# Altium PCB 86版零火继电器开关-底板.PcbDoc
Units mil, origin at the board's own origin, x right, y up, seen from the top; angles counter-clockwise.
Board outline 2181.33 x 2307.03 mil, 2 copper layers (Top Layer, Bottom Layer); 71 components, 44 nets, 206 pads, 150 vias.
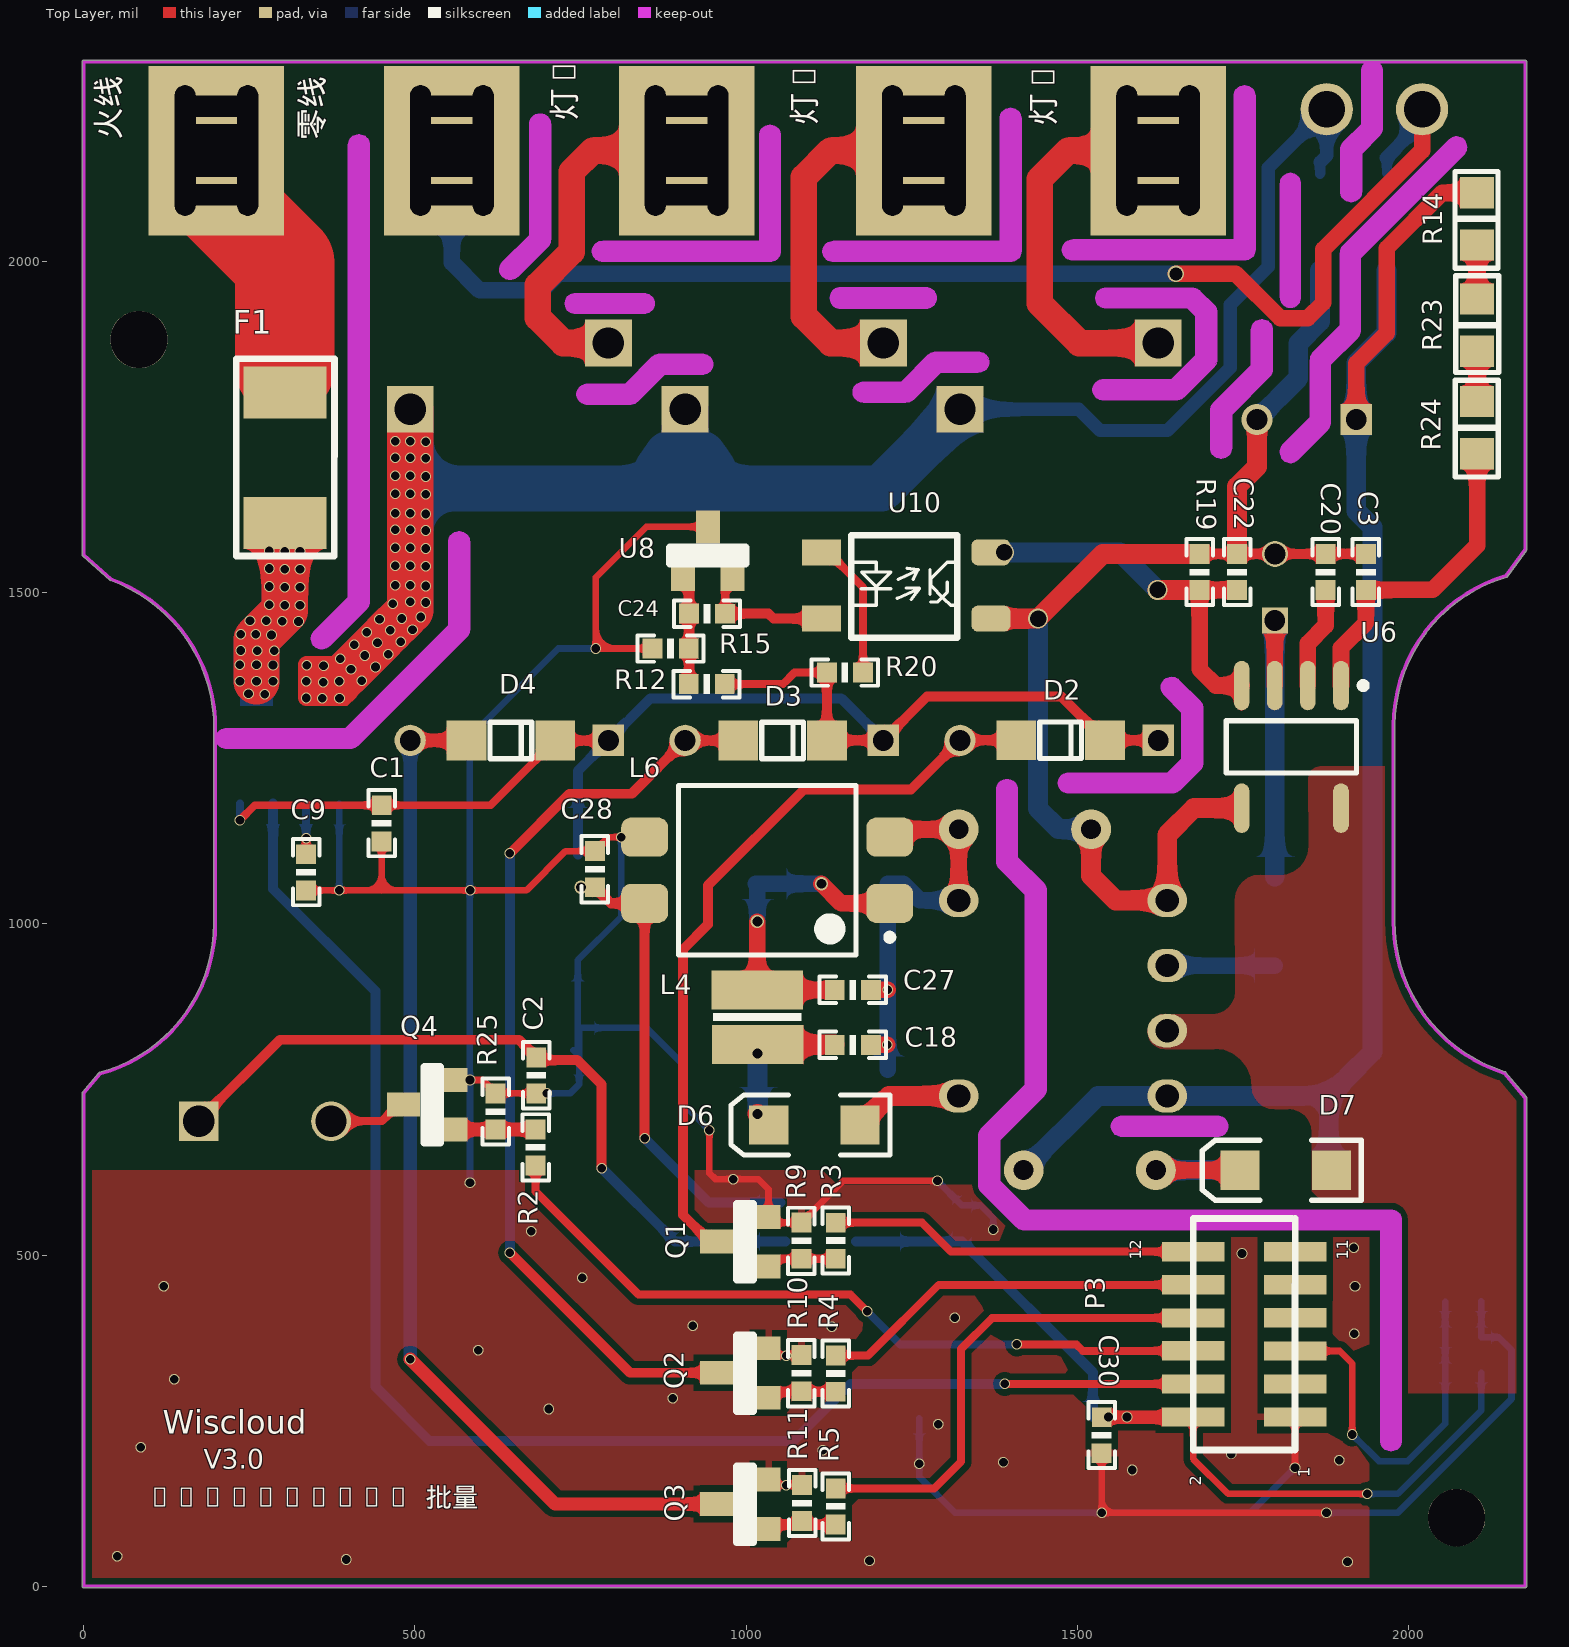
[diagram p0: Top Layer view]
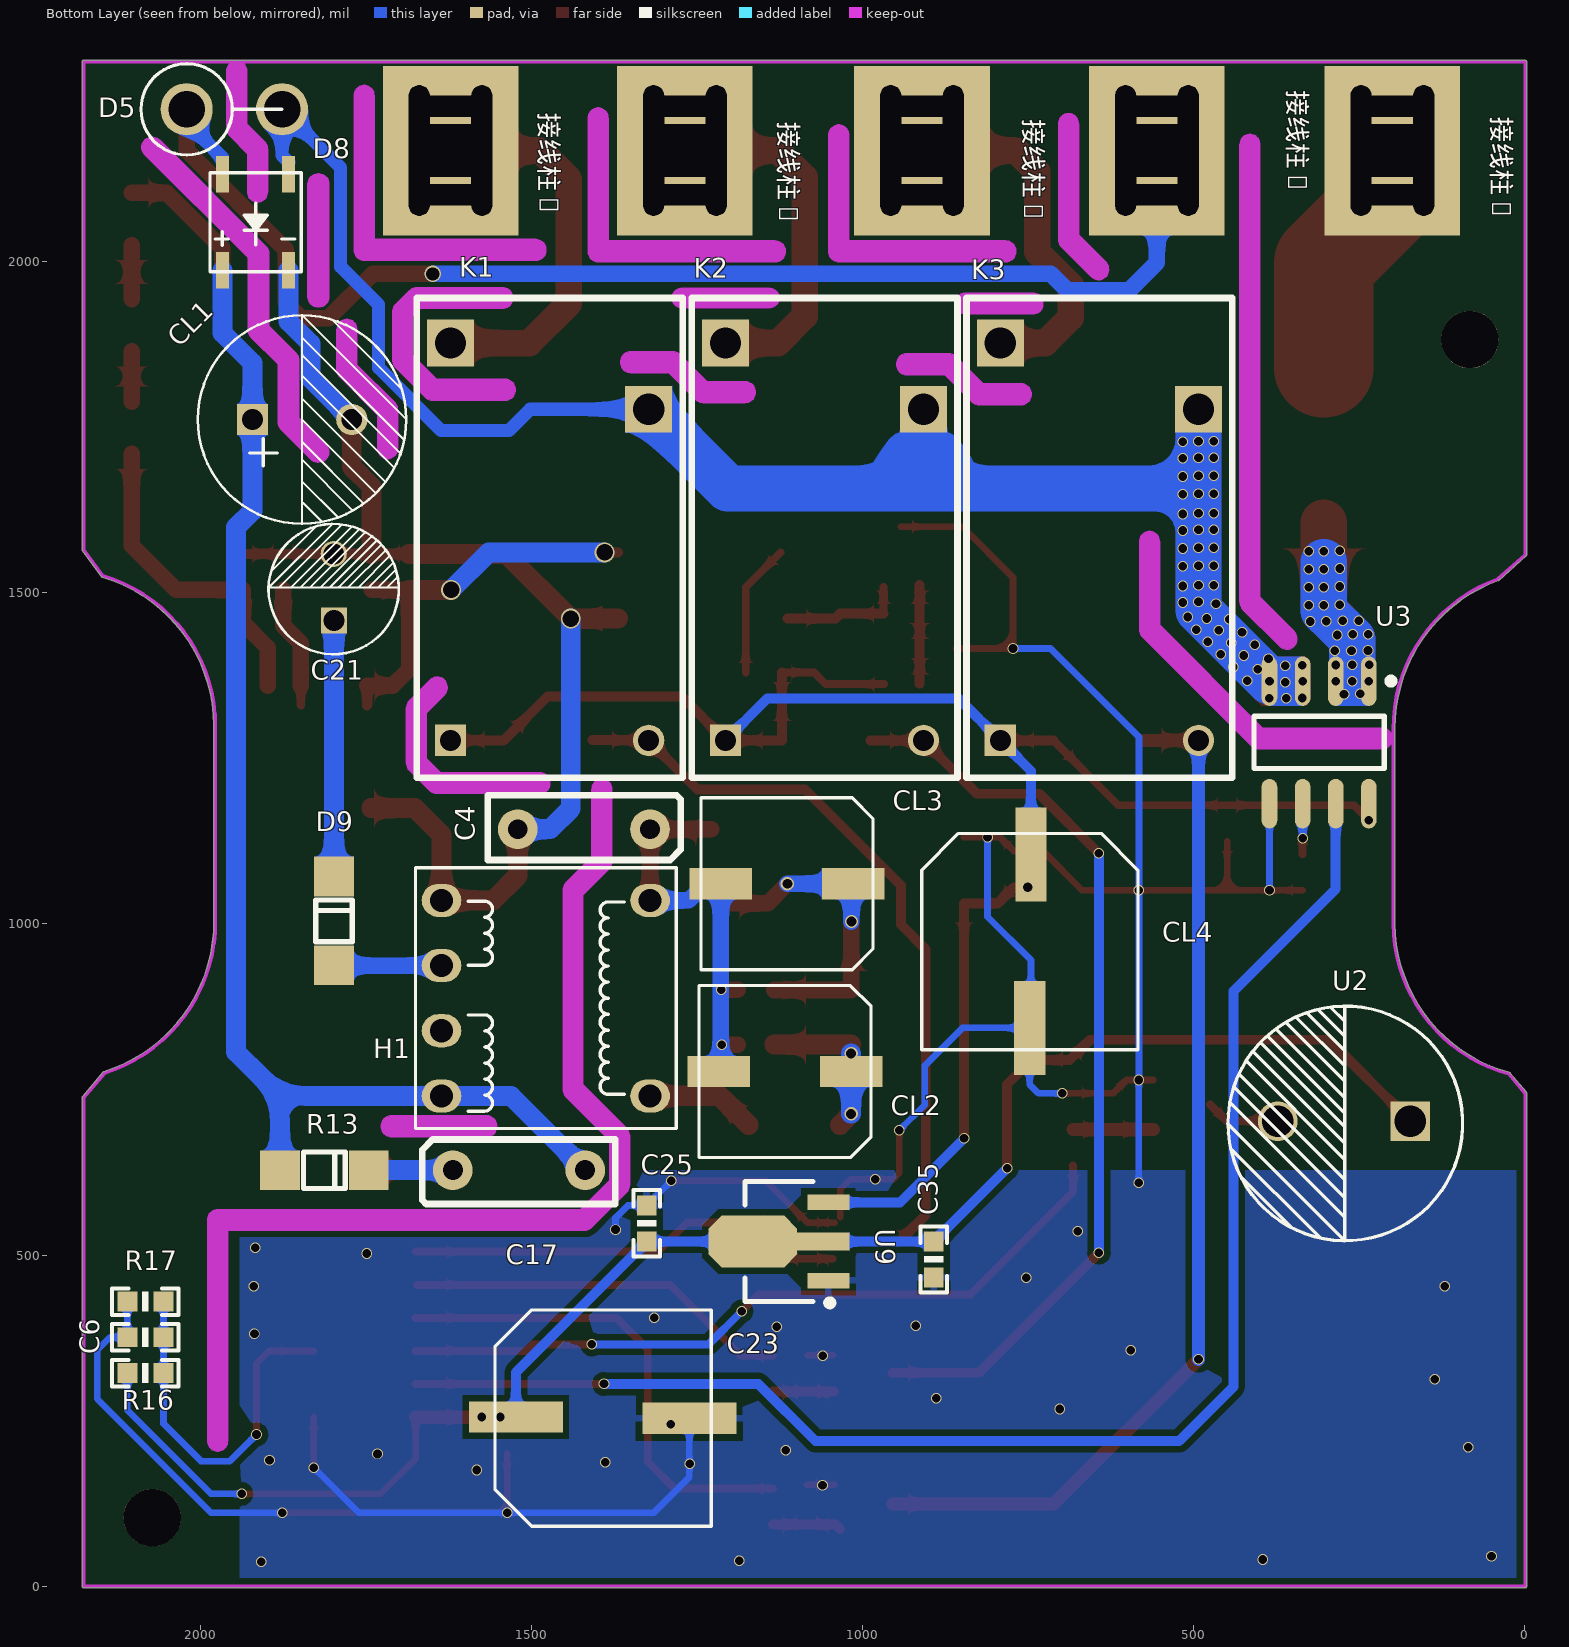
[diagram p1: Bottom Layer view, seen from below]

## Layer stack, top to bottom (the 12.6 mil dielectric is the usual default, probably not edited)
Top Solder: solder mask 0.4, Solder Resist, Dk 3.5
Top Layer: signal copper 1.4
Dielectric1: dielectric 12.6, FR-4, Dk 4.8
Bottom Layer: signal copper 1.4
Bottom Solder: solder mask 0.4, Solder Resist, Dk 3.5

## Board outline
-2.52,0 ccw(c0,0) 0.7,-2.42 ccw(c1.4,0) 1.4,-2.52 2176.3,-2.52 ccw(c2176.3,0) 2178.81,0 2178.81,737.5 ccw(c2176.3,737.5) 2178.23,739.12 2178.22,739.12 cw(c2176.3,737.5) 2178.23,739.11 2178.22,739.12 2147.11,776.25 2147.1,776.26 cw(c2145.17,774.64) 2147.11,776.25 2147.1,776.26 ccw(c2145.17,774.64) 2145.93,777.04 cw(c2217.11,1003.35) 1979.87,1004.79 ccw(c1977.36,1004.81) 1979.87,1004.81 1979.87,1299.99 cw(c2214.26,1298.6) 2148.26,1523.51 cw(c2214.26,1298.6) 2148.28,1523.51 2148.26,1523.51 ccw(c2147.57,1525.93) 2149.6,1524.44 2178.33,1563.61 ccw(c2176.3,1565.1) 2178.81,1565.1 2178.81,2302 ccw(c2176.3,2302) 2176.3,2304.51 0,2304.51 ccw(c0,2302) -2.52,2302 -2.52,1557.7 ccw(c0,1557.7) -1.68,1555.83 39.28,1519.2 ccw(c40.95,1521.07) 40.12,1518.7 ccw(c-40.79,1295.71) 40.1,1518.71 40.12,1518.7 cw(c-40.79,1295.71) 196.42,1295.71 cw(c-40.79,1295.71) 196.42,1294.33 cw(c-40.79,1295.71) 196.42,1294.31 196.42,1294.29 cw(c198.93,1294.29) 196.42,1294.33 196.42,1294.29 196.42,1000.5 cw(c-37.96,1001.89) 23.78,775.79 cw(c-37.96,1001.89) 23.75,775.78 ccw(c24.42,773.35) 22.48,774.96 22.49,774.98 cw(c24.42,773.35) 23.78,775.79 22.48,774.96 -1.91,746.03 -1.92,746.02 -1.91,746.03 ccw(c0,744.4) -2.52,744.4
cut-out: 1356.12,594.68 cw(c1367.24,605.85) 1351.48,605.85 1351.48,680.13 cw(c1367.24,680.13) 1356.12,691.3 1356.09,691.28 1421.8,756.98 1421.8,1044.24 1382.9,1083.14 1382.92,1083.11 cw(c1394.05,1094.28) 1378.28,1094.28 1378.28,1202.85 cw(c1394.05,1202.85) 1409.81,1202.85 1409.81,1100.81 1448.71,1061.91 1448.68,1061.94 cw(c1437.56,1050.77) 1453.32,1050.77 1453.32,750.45 cw(c1437.56,750.45) 1448.68,739.28 1448.71,739.31 1383,673.6 1383,612.38 1426.64,568.74 1974.12,568.74 cw(c1974.12,552.98) 1989.89,552.98 1989.89,219.57 cw(c1974.12,219.57) 1958.36,219.57 1958.36,537.21 1420.11,537.21 cw(c1420.11,552.98) 1408.94,541.85 1408.97,541.83
cut-out: 1487.4,1197.22 cw(c1487.4,1212.98) 1487.4,1228.74 1637.14,1228.74 1658.26,1249.86 1658.26,1319.36 1631.48,1346.15 cw(c1642.62,1357.29) 1653.77,1368.44 1685.17,1337.04 1685.14,1337.06 cw(c1674.02,1325.89) 1689.78,1325.89 1689.78,1243.33 cw(c1674.02,1243.33) 1685.14,1232.17 1685.17,1232.19 1654.81,1201.83 1654.84,1201.86 cw(c1643.67,1212.98) 1643.67,1197.22
cut-out: 215.76,1264.42 cw(c215.76,1280.18) 215.76,1295.95 395.76,1295.95 551.05,1451.24 551.05,1577.22 cw(c566.81,1577.22) 582.57,1577.22 582.57,1444.71 cw(c566.81,1444.71) 577.93,1433.54 577.96,1433.56 413.43,1269.04 413.46,1269.06 cw(c402.29,1280.18) 402.29,1264.42
cut-out: 1810.85,1723.61 ccw(c1821.99,1712.47) 1833.14,1701.32 1878.44,1746.62 1878.42,1746.6 ccw(c1867.29,1757.77) 1883.06,1757.77 1883.06,1844.94 1923.74,1885.62 1923.72,1885.6 ccw(c1912.6,1896.77) 1928.36,1896.77 1928.36,2006.1 2084.22,2161.96 ccw(c2073.07,2173.1) 2088.83,2173.1 ccw(c2073.07,2173.1) 2061.92,2184.25 1901.5,2023.83 ccw(c1912.65,2012.68) 1901.36,2023.68 cw(c1912.6,2012.62) 1901.5,2023.83 1901.36,2023.68 ccw(c1912.6,2012.62) 1896.83,2012.62 1896.83,1903.3 1856.15,1862.62 1856.17,1862.64 ccw(c1867.29,1851.47) 1851.53,1851.47 1851.53,1764.3
cut-out: 1898.13,2105.8 1898.13,2169.86 cw(c1913.89,2169.86) 1902.77,2181.03 1902.75,2181.01 1929.57,2207.83 1929.57,2288.24 cw(c1945.33,2288.24) 1961.09,2288.24 1961.09,2202.3 cw(c1945.33,2202.3) 1959.04,2194.53 cw(c1944.4,2200.38) 1955.55,2189.23 1929.66,2163.34 1929.66,2105.8 cw(c1913.89,2105.8)
cut-out: 1131.88,1999.97 cw(c1131.88,2015.73) 1131.88,2031.5 1383.76,2031.5 1383.76,2216.8 cw(c1399.53,2216.8) 1415.29,2216.8 1415.29,2015.73 cw(c1399.53,2015.73) 1399.53,1999.97
cut-out: 1493.45,2002.18 cw(c1493.45,2017.94) 1493.45,2033.71 1737.14,2033.71 1737.14,2250.7 cw(c1752.91,2250.7) 1768.67,2250.7 1768.67,2017.94 cw(c1752.91,2017.94) 1752.91,2002.18
cut-out: 1806.31,1946.74 ccw(c1822.07,1946.74) 1837.83,1946.74 1837.83,2117.87 ccw(c1822.07,2117.87) 1806.31,2117.87
cut-out: 1701.67,1718.59 1701.67,1775.91 cw(c1717.43,1775.91) 1706.31,1787.08 1706.28,1787.06 1763.28,1844.06 1763.28,1897.42 cw(c1779.04,1897.42) 1794.81,1897.42 1794.81,1837.53 cw(c1779.04,1837.53) 1790.17,1826.36 1790.19,1826.38 1733.19,1769.38 1733.19,1718.59 cw(c1717.43,1718.59)
cut-out: 1539.69,1822.51 1643.26,1822.51 1679.33,1858.58 1679.33,1917.46 1667.15,1929.63 1543.9,1929.63 cw(c1543.9,1945.39) 1543.9,1961.16 1673.68,1961.16 cw(c1673.68,1945.39) 1684.85,1956.52 1684.83,1956.54 1706.24,1935.13 1706.21,1935.16 cw(c1695.09,1923.99) 1710.85,1923.99 1710.85,1852.05 cw(c1695.09,1852.05) 1706.21,1840.88 1706.24,1840.9 1660.94,1795.6 1660.96,1795.63 cw(c1649.79,1806.75) 1649.79,1790.98 1539.69,1790.98 cw(c1539.69,1806.75)
cut-out: 1177.31,1787.35 cw(c1177.31,1803.11) 1177.31,1818.87 1234.84,1818.87 1275.53,1859.56 1275.5,1859.53 cw(c1286.67,1848.41) 1286.67,1864.17 1350.74,1864.17 cw(c1350.74,1848.41) 1366.5,1848.41 cw(c1350.74,1848.41) 1350.74,1832.65 1293.2,1832.65 1252.52,1791.96 1252.54,1791.99 cw(c1241.37,1803.11) 1241.37,1787.35
cut-out: 760.48,1784.23 cw(c760.48,1799.99) 760.48,1815.76 818.01,1815.76 858.7,1856.44 858.67,1856.42 cw(c869.84,1845.29) 869.84,1861.06 933.91,1861.06 cw(c933.91,1845.29) 949.67,1845.29 cw(c933.91,1845.29) 933.91,1829.53 876.37,1829.53 835.69,1788.85 835.71,1788.87 cw(c824.54,1799.99) 824.54,1784.23
cut-out: 742.77,1921.33 cw(c742.77,1937.1) 742.77,1952.86 845.64,1952.86 cw(c845.64,1937.1) 861.41,1937.1 cw(c845.64,1937.1) 845.64,1921.33
cut-out: 1142.32,1929.63 1272.11,1929.63 ccw(c1272.11,1945.39) 1287.87,1945.39 ccw(c1272.11,1945.39) 1272.11,1961.16 1142.32,1961.16 ccw(c1142.32,1945.39)
cut-out: 783.85,2000.09 cw(c783.85,2015.85) 783.85,2031.61 1020.42,2031.61 1020.42,2191.12 cw(c1036.19,2191.12) 1051.95,2191.12 1051.95,2015.85 cw(c1036.19,2015.85) 1036.19,2000.09
cut-out: 654.98,1977.43 cw(c643.83,1988.57) 632.69,1999.72 673.37,2040.4 673.37,2208.02 cw(c689.13,2208.02) 704.9,2208.02 704.9,2033.87 cw(c689.13,2033.87) 700.26,2022.7 700.28,2022.73
cut-out: 370.57,1419.5 cw(c359.42,1430.65) 348.27,1441.8 399.62,1493.15 399.62,2176.79 cw(c415.39,2176.79) 431.15,2176.79 431.15,1486.62 cw(c415.39,1486.62) 426.51,1475.45 426.53,1475.47
cut-out: 1567.63,678.76 cw(c1567.63,694.53) 1567.63,710.29 1712.05,710.29 cw(c1712.05,694.53) 1727.81,694.53 cw(c1712.05,694.53) 1712.05,678.76

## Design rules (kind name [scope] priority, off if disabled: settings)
Clearance [All] p1: gap=10 ignorepadtopadclearanceinfootprint=FALSE except(0: Arc-Hole Track-Hole SMDPad-Hole THPad-Hole Via-Hole Fill-Hole Poly-Hole Region-Hole Text-Hole)
HoleSize [All] p1: absolutevalues=TRUE maxlimit=300 minlimit=1 maxpercent=80.000 minpercent=20.000
MinimumSolderMaskSliver [All] p1: minsoldermaskwidth=7
PlaneConnect [InNet('GND')] p1: planeconnectstyle=Direct reliefexpansion=20 reliefentries=4 reliefconductorwidth=10 reliefairgap=10
PolygonConnect via [IsVia] p1: connectstyle=Direct reliefconductorwidth=10 reliefentries=4 polygonreliefangle="90 Angle" airgapwidth=10
PolygonConnect "GND _PAD" [InNet('GND')] p2: connectstyle=Relief reliefconductorwidth=10 reliefentries=4 polygonreliefangle="90 Angle" airgapwidth=10
PolygonConnect PolygonConnect_1 [All] p3: connectstyle=Direct reliefconductorwidth=10 reliefentries=4 polygonreliefangle="90 Angle" airgapwidth=10
RoutingVias [All] p1: holewidth=13 width=16 viastyle="Through Hole" minholewidth=12 minwidth=15 maxholewidth=28 maxwidth=50
SilkToSilkClearance [All] p1: silktosilkclearance=2
SilkToSolderMaskClearance [IsPad] p1: minsilkscreentomaskgap=2 clearancetoexposedcopper=TRUE
SolderMaskExpansion [All] p1: expansion=4
Width [All] p1: maxlimit=200 minlimit=10 preferedwidth=12
25 further rules are at their usual default settings.

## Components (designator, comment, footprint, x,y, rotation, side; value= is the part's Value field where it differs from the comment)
C1 "106" 0603P 449.83,1179.29 r270 top
C2 "104" 0603P 683.27,798.64 r270 top
C3 "103" 0603p 1936.11,1504.44 r90 top
C4 "471/1KV" 200mil 1521.09,1142.98 r0 bottom
C6 "104" 0603P 2110.51,375.9 r180 bottom
C9 "2.2uF" 0603P 335.77,1105.31 r270 top
C17 "222" 200mil 1419.24,628.28 r180 bottom
C18 "104" 0603P 1134.08,817.42 r0 top
C20 "330P" 0603P 1875.33,1504.44 r90 top
C21 "25V/47UF" CAP5*2 1795.78,1509.74 r90 bottom value=4.7uF/400V
C22 "103" 0603P 1741.58,1504.44 r90 top
C23 "6.3V1000uF" CAP8*10.2 1523.76,255.46 r90 bottom
C24 "103" 0603p 914.02,1468.67 r0 top
C25 "104" 0603P 1326.21,574.98 r270 bottom value=0.1uF
C27 "104" 0603P 1134.08,900.48 r0 top
C28 "104" 0603P 771.75,1055.53 r90 top
C30 "104" 0603P 1537.17,255.2 r270 top
C35 "104" 0603P 892.68,520.48 r270 bottom
CL1 "4.7uf/400V" CAP8*12 1921.62,1761.7 r180 bottom value=4.7uF/400V
CL2 "50V47uF" CAP6.3*5.4 1017.52,777.17 r270 bottom value=4.7uF/400V
CL3 "16V220uF" CAP6.3*5.4 1014.56,1060.79 r270 bottom value=4.7uF/400V
CL4 "10V/1000UF" CAP8*10.2 746.01,1105.07 r180 bottom value=4.7uF/400V
D2 "1N4148" 1206 1408.15,1277.54 r0 top
D3 "1N4148" 1206 988.31,1277.07 r0 top
D4 "1N4148" 1206 577.91,1277.07 r0 top
D5 "P6KE550AC" DO-15立式 2020.97,2229.89 r180 bottom
D6 "SS110" 3.2X1.6X1.1 1103.18,696.6 r180 top
D7 "RS1M" 3.2X1.6X1.1 1815.08,628.12 r180 top
D8 "LX10M" MBCN 1866.98,1986.89 r0 bottom
D9 "1N4148" 1206 1798.53,937.79 r90 bottom
F1 "250V/10A" 2410 304.74,1606.82 r90 top
H1 "EE10立式4+2" EE10-6 1641.26,782.54 r180 bottom
K1 "HRS3FNH-S-DC5V-A" SJ-S-105 1622.5,1277.29 r90 bottom
K2 "HRS3FNH-S-DC5V-A" SJ-S-105 1207.32,1277.29 r90 bottom
K3 "HRS3FNH-S-DC5V-A" SJ-S-105 792.15,1277.29 r90 bottom
L4 "10uH" CD32NP 1017.12,858.72 r90 top
L6 "ZJYS51R5-2PT-01" SOP-4N 1031.54,1081.22 r180 top
P3 "贴片排母" 贴片排母1.27MM2*6 1675.83,206.13 r90 top locked
Q1 "SS8050" SOT23 1033.94,482.76 r90 top
Q2 "SS8050" SOT23 1033.94,284.54 r90 top
Q3 "SS8050" SOT23 1033.94,86.32 r90 top
Q4 "SS8050" SOT23 561.38,689.58 r90 top
R2 "330Ω" 0603P 682.24,689.68 r270 top
R3 "510Ω" 0603P 1135.57,548.92 r270 top
R4 "510Ω" 0603P 1135.57,348.21 r270 top
R5 "510Ω" 0603P 1135.57,147.49 r270 top
R9 "4.7K" 0603P 1083.53,494.47 r90 top
R10 "4.7K" 0603P 1083.53,294.41 r90 top
R11 "4.7K" 0603P 1084.72,98.43 r90 top
R12 "3K/1%" 0603P 913.45,1362.23 r0 top value=100k
R13 "100K" 1206 1880.04,628.12 r180 bottom value=100k
R14 "680K" 0805 2103.77,2025.42 r90 top value=100k
R15 "2.4K" 0603P 859.02,1416.07 r0 top value=100k
R16 "10K欧姆" 0603p 2110.51,321.95 r180 bottom
R17 "2K" 0603P 2110.51,429.86 r180 bottom
R19 "10K" 0603P 1684.96,1504.44 r90 top value=100k
R20 "100Ω" 0603P 1122.17,1379.84 r0 top value=100k
R23 "680K" 0805 2103.86,1943.8 r270 top value=100k
R24 "680K" 0805 2103.96,1710.17 r90 top value=100k
R25 "4.7K" 0603P 621.86,689.64 r90 top
U2 "SPEAK" Speak-9*5.5 273.38,702.29 r0 bottom
U3 "ACS712-5" SO8_L 310.77,1274.3 r270 bottom
U6 "THX208H" SO8_L_6 1755.82,1406.15 r270 top
U8 "TL431" SOT23 904.88,1521.06 r0 top
U9 "LM1117-3.3V" SOT89M 1126.59,520.48 r0 bottom
U10 "356T-WC" "SOP4 - EL357N" 1113.96,1561.22 r0 top
接线柱1 "接线柱" 5*6*10 200.21,2168 r0 bottom locked
接线柱2 "接线柱" 5*6*10 555.8,2168 r0 bottom locked
接线柱3 "接线柱" 5*6*10 910.5,2168 r0 bottom locked
接线柱4 "接线柱" 5*6*10 1268.5,2168 r0 bottom locked
接线柱5 "接线柱" 5*6*10 1622.5,2168 r0 bottom locked

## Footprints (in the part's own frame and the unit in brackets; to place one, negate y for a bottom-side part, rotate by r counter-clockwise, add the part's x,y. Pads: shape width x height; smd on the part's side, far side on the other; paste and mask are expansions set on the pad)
3.2X1.6X1.1 [mm] "SMT LED; 2 Flat Leads"
  rect 1.5x1.5 smd: 1(-1.75,0) 2(1.75,0)
  silkscreen extent -2.9,-1.15 3.2,1.15, body extent -2.29,-1.43 2.31,1.27, height 2.4
5*6*10 [mm]
  oval 0.8x5 hole 0.8 slot 5 at 90 deg: 1(-1.201,-0.003) 1(1.201,-0.003)
  oval 3.2x0.8 hole 0.8 slot 3.2 at 0 deg: 1(0,-1.699) 1(0,1.699)
  rect 5.2x6.5 hole 2 square: 1(0,0)
200mil [mil]
  round 60 hole 30: 1(0,0) 2(-199.8,0)
  silkscreen extent -246,-51 45,46, body extent -208,-41 12,49, height 242
0603P [mil] "Chip Capacitor, 2-Leads, Body 1.6x0.8mm, IPC Medium Density"
  rect 30x30 smd: 1(0,0) 2(54.5,-0.06)
  silkscreen extent -23,-20 77,20
0603p [mil] "Chip Capacitor, 2-Leads, Body 1.6x0.8mm, IPC Medium Density"
  rect 30x30 smd: 1(0,0) 2(54.5,-0.06)
  silkscreen extent -23,-20 77,20, body extent -6,-16 57,16, height 18
0805 [mm]
  rect 1.2x1.3 smd: 1(0,0) 2(2,0)
  silkscreen extent -0.89,-0.81 2.82,0.84, body extent 0.01,-0.63 2.01,0.63, height 0.55
1206 [mil]
  rect 60x60 smd: 1(0,0) 2(133.86,0)
  silkscreen extent 35,-28 98,28
2410 [mm]
  rect 2x3.18 smd: 1(-0.028,0.027) 2(4.972,0.027)
  silkscreen extent -1.3,-1.87 6.27,1.9
CAP5*2 [mm]
  rect 1x1 hole 0.8: 1(-1.31,0.07)
  round 1 hole 0.8: 2(1.25,0.08)
  silkscreen extent -2.6,-2.42 2.4,2.58
CAP6.3*5.4 [mm]
  rect 1.2x2.4 smd: 1(0,0) 2(0.001,-5.074)
  silkscreen extent -3.3,-5.84 3.3,0.76
CAP8*10.2 [mm]
  rect 1.2x3.6 smd: 1(0,0) 2(-0.051,-6.655)
  silkscreen extent -4.19,-7.49 4.11,0.8, body extent -4.36,-8.15 4.14,1.55, height 10.5
CAP8*12 [mm]
  rect 1.2x1.2 hole 0.8: 1(0,0)
  round 1.2 hole 0.8: 2(3.81,0)
  silkscreen extent -2.1,-4 5.9,4
CD32NP [mm] "CD32"
  rect 1.5x3.5 smd mask+0: 1(-1.04,-0.012) 2(1.057,0)
  silkscreen extent -0.13,-1.69 0.17,1.71, body extent -1.73,-1.47 1.72,1.53, height 2
DO-15立式 [mm] "直插器件，引脚间距5mm"
  round 2 hole 1.4: 1(0,0.01) 2(3.658,0.01)
  silkscreen extent -1.75,-1.74 3.66,1.76
EE10-6 [mil]
  oval 60x50 hole 35: 1(5.12,-42.13) 2(5.12,56.3) 3(5.12,154.72) 4(5.12,253.15) 5(320.08,253.15) 6(320.08,-42.13)
  silkscreen extent -34,-91 359,302
MBCN [mm]
  rect 0.5x1.4 smd: 1(2.54,0) 2(0,0) 3(2.54,-3.7) 4(0,-3.7)
  silkscreen extent -0.48,-3.75 3.02,0.05
SJ-S-105 [mm]
  rect 1.2x1.2 hole 0.8: 1(0,0)
  round 1.2 hole 0.8: 2(0,-7.6)
  round 1.2 on Bottom Overlay: 2(15.55,-7.64)
  rect 1.8x1.8 hole 1.2: 3(12.7,-7.6) 4(15.24,0)
  silkscreen extent -1.43,-8.9 16.97,1.3
SO8_L [mm] "SOIC, 8-Leads, Body 4.9x3.9mm, Pitch 1.27mm, IPC High Density"
  oval 1.9x0.6 smd: 1(-2.35,1.905) 2(-2.35,0.635) 3(-2.35,-0.635) 4(-2.35,-1.905) 5(2.35,-1.905) 6(2.35,-0.635) 7(2.35,0.635) 8(2.35,1.905)
  silkscreen extent -2.47,-2.5 1,2.88, body extent -2.98,-2.5 3.07,2.52, height 1.6
SO8_L_6 [mm]
  oval 1.9x0.6 smd: 1(1.17,3.625) 2(1.17,2.355) 3(1.17,1.085) 4(1.17,-0.185) 5(5.87,-0.185) 8(5.87,3.625)
  silkscreen extent 1.05,-0.78 4.52,4.6, body extent 1.52,-0.78 5.52,4.22, height 1.75
"SOP4 - EL357N" [mm]
  rect 1.5x1 smd: 1(0,0) 2(0,-2.54)
  rrect50% 1.5x1 smd: 3(6.5,-2.54) 4(6.5,0)
  round 0.508 on Top Overlay: 5(0.363,0.927)
  silkscreen extent 1.14,-3.27 5.21,0.66
SOP-4N [mm]
  rrect50% 1.8x1.5 smd: 1(-4.713,1.271) 2(-4.713,-1.269) 3(4.687,-1.269) 4(4.687,1.271)
  silkscreen extent -4.84,-3.25 3.39,3.25, body extent -2.51,-3.25 2.49,3.25, height 5.08
SOT23 [mil]
  rect 36x36 smd: 1(0,0) 2(74.8,0)
  rect 36x50 smd: 3(37.79,78.74)
  silkscreen extent -20,24 94,47
SOT89M [mm] "SOT89, 3-Leads, Body 4.5x2.4 mm, Pitch 1.5mm, Lead Span 4.1mm, IPC Low Density"
  rect 1.6x0.6 smd: 1(-1.9,1.5) 3(-1.9,-1.5)
  rect 2x0.7 smd: 2(-1.7,0)
  oct 3.4x2 smd: 2(1,0)
  silkscreen extent -2.07,-2.3 1.3,2.47, body extent -1.3,-2.3 1.3,2.3, height 1.6
Speak-9*5.5 [mil] "SOIC, 8-Leads, Body 4.9x3.9mm, Pitch 1.27mm, IPC High Density"
  rect 60x60 hole 47.24: 1(-100,0)
  round 60 hole 47.24: 2(100,0)
  silkscreen extent -179,-174 176,181
贴片排母1.27MM2*6 [mm]
  rect 0.74x2.4 smd: 1(1.252,-3.894) 2(1.252,0.015) 3(2.522,-3.894) 4(2.522,0.015) 5(3.785,-3.896) 6(3.792,0.015) 7(5.062,-3.894) 8(5.055,0.013) 9(6.325,-3.896) 10(6.325,0.013) 11(7.595,-3.896) 12(7.595,0.013)
  silkscreen extent -0.01,-3.9 8.87,0.02

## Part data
C1 C2 C3 C6 C9 C18 C20 C22 C24 C27 C28 C30 C35: library part C, "贴片电容"
C4: library part C, "高压瓷片电容 471/1KV"
C17: library part C, "涤纶电容 222/1KV"
C21: library part Cap2, "直插电解电容 5*11"
C23: library part CAP+, "贴片电解电容8*10.2"
C25: library part Cap, "贴片电容"
CL1: library part Cap2, "直插电解电容 8*12"
CL2 CL3: library part Cap2, "贴片电解电容 6.3*7.7"
CL4: library part Cap2, "贴片电解电容 8*10.2"
D2 D3 D4 D7 D9: library part Diode, "贴片二极管"
D5: library part TVS, "直插式双向瞬抑制二极管"
D6: library part Diode, "贴片整流二极管"
D8: library part MB6S, "贴片整流桥"
F1: library part "Fuse Thermal", "2410贴片保险丝"
H1: library part EE13立式4+4, "变压器"
K1 K2 K3: library part Relay-SPST, "5V继电器"
L4: library part INDUCTOR2, "CD32贴片电感"
L6: library part 共模电感, "贴片电感"
P3: library part "Header 6X2", "贴片排母1.27MM2*6"
Q1 Q2 Q3: library part 2N3904, "贴片三极管"
Q4: "贴片三极管"
R2 R25: library part RES2, "贴片电阻"
R3 R4 R5 R9 R10 R11 R12 R13 R14 R15 R19 R20 R23 R24: library part Res2, "贴片电阻"
R16: library part "Res Varistor", "贴片温敏电阻,负温度系数 3950"
R17: library part R, "贴片电阻"
U2: "3.3V有源蜂鸣器，9*5.5"
U3: library part Component_1, "贴片电流检测芯片，5A，不焊接不用料"
U6: library part CON8, "贴片电源管理芯片"
U8: "贴片IC"
U9: library part LM1117, "贴片IC"
U10: library part NEC2701, "贴片光耦，C档"
接线柱1 接线柱2 接线柱3 接线柱4 接线柱5: "接线铜柱"

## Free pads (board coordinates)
  round 86.61 hole 86.61: 1(2073.04,103.43) 2(83.28,1882.57)

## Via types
v1: diameter 16, hole 13, Top Layer to Bottom Layer, tented both sides, 131 vias
v2: diameter 16, hole 13, Top Layer to Bottom Layer, 10 vias
v3: diameter 20, hole 15, Top Layer to Bottom Layer, tented both sides, 5 vias
v4: diameter 30, hole 25, Top Layer to Bottom Layer, tented both sides, 3 vias
v5: diameter 25, hole 20, Top Layer to Bottom Layer, tented both sides, 1 vias

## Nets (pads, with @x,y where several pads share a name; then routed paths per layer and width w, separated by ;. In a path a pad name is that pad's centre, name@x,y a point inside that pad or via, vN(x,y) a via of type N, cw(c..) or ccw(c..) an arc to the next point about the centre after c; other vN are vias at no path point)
5V: C1.1 C28.1 CL4.1 D2.2 D3.2 D4.2 K1.1 K2.1 K3.1 L6.4 R12.2 R20.1 U3.8 U9.3 | length 2815.1
  Top Layer w12: v1(235.77,1156.95) 258.12,1179.29 C1.1 613.99,1179.29 D4.2 ; R12.2 1055.73,1362.17 1073.4,1379.84 R20.1
  Top Layer w15: D4.2 K3.1@791.93,1277.07 ; v3(750.85,1055.53) C28.1 796.12,1031.16 L6.4 v1(847.02,676.26) ; D3.2 R20.1 ; D3.2@1122.39,1277.29 K2.1 1273.4,1343.37 1476.19,1343.37 D2.2 1542.27,1277.29 K1.1
  Bottom Layer w12: v1(235.77,1156.95) U3.8
  Bottom Layer w15: CL4.1 746.01,1231.15 K3.1 855.69,1340.83 1143.77,1340.83 K2.1 ; v1(847.02,676.26) 943.76,579.53 U9.3
5V-AC: C18.1 CL2.1 D6.2 L4.1 | length 231
  Top Layer w30: v3(1017.52,713.36) D6.2 ; L4.1 C18.1@1133.74,817.76
  Bottom Layer w30: v3(1017.52,713.36) CL2.1 v3(1017.52,804.5)
+3V3: C2.1 C23.1 C25.2 C30.1 C35.1 P3.2 R16.1 U2.1 U9.2 | length 2523.8
  Top Layer w10: v1(1547.46,255.46) 1616.14,255.46 P3.2@1635.86,255.46 ; P3.2 1675.23,192.27 1728.03,139.47 v1(1937.98,139.47)
  Top Layer w15: U2.1 296.25,825.15 656.94,825.15 687.55,794.54 745.16,794.54 782.03,757.68 v1(782.03,631.13)
  Top Layer w20: C30.1 1675,255.2 P3.2
  Bottom Layer w10: C23.1 v1(1547.46,255.46) ; v1(1937.98,139.47) 1984.36,139.47 2110.51,265.62 R16.1
  Bottom Layer w15: v1(782.03,631.13) C35.1 U9.2@1059.66,520.48 ; U9.2@1165.96,520.48 C25.2 1523.76,323 C23.1
  other v2: 1575.39,255.46
A: K1.4 接线柱5.1 | length 655
  Top Layer w40: K1.4 1503.55,1877.29 1443.64,1937.2 1443.64,2124.95 1486.69,2168 接线柱5.1@1622.5,2168
  Top Layer w60: 接线柱5.1@1622.5,2101.1 接线柱5.1@1622.5,2168
B: K2.4 接线柱4.1 | length 611
  Top Layer w40: K2.4 1128.13,1877.29 1087.54,1917.87 1087.54,2127.77 1127.76,2168 接线柱4.1@1268.5,2168
  Top Layer w60: 接线柱4.1@1268.5,2101.1 接线柱4.1@1268.5,2168
BTA1_CONTROL: P3.8 R5.1 | length 746.1
  Top Layer w12: R5.1 1284.12,147.49 1324.7,188.07 1324.7,358.14 1371.69,405.13 P3.8
BTA2_CONTROL: P3.10 R4.1 | length 581.6
  Top Layer w12: R4.1 1184.22,348.21 1291.15,455.13 P3.10@1672.9,455.13
BTA3_CONTROL: P3.12 R3.1 | length 557.9
  Top Layer w12: R3.1 1265.68,548.92 1309.47,505.13 P3.12
C: K3.4 接线柱3.1 | length 617.5
  Top Layer w40: K3.4 724.34,1877.29 685.85,1915.77 685.85,1964.41 736.67,2015.23 736.67,2135.93 768.74,2168 接线柱3.1@910.5,2168
  Top Layer w60: 接线柱3.1@910.5,2101.1 接线柱3.1@910.5,2168
CT: P3.4 U3.7 | length 2249.3
  Top Layer w12: v2(1390.76,305.43) P3.4
  Bottom Layer w15: U3.7 285.77,1052.95 440.23,898.48 440.23,301.13 522.16,219.21 1071.54,219.21 1157.76,305.43 v2(1390.76,305.43)
GND: C1.2 C2.2 C6.1 C9.2 C23.2 C25.1 C28.2 C30.2 C35.2 CL4.2 L6.3 P3.1 Q1.2 Q2.2 Q3.2 Q4.2 R9.2 R10.2 R11.2 R15.1 R17.1 R25.2 U3.5 U8.3 U9.1 | length 5594.2
  Top Layer w10: C9.2 v1(385.77,1050.81) 426.3,1050.81 ; C1.2 449.77,1074.28 ; Q4.2 v1(583.2,764.38) 601.68,764.38 R25.2 C2.2 v1(699,744.14) ; L6.3 v1(811.53,1131.16) 792.94,1131.16 C28.2 727.63,1110.03 668.41,1050.81 v1(583.27,1050.81) 473.23,1050.81 ; R15.1 803.08,1416.07 ; U8.3 849.59,1599.8 773.17,1523.38 773.17,1445.98 ; v1(944.77,688.46) 944.77,623.69 953.76,614.71 v1(981.01,614.71) 1018.53,614.71 1033.94,599.3 Q1.2 ; Q3.2@1042.14,152.93 R11.2 ; Q1.2@1042.54,548.97 R9.2 1146.62,611.98 v1(1289.2,611.98) ; Q2.2@1044.37,348.91 R10.2 ; C30.2 1537.1,131.17 ; v1(1829.13,178.99) P3.1 ; v1(1876.57,110.72) 1557.56,110.72 ; 426.3,1050.81 ccw(c426.3,1074.28) 449.77,1074.28 ; 426.3,1050.81 449.77,1050.81 ; 449.77,1050.81 473.23,1050.81 ; 449.77,1050.81 449.77,1074.28 ; 449.77,1074.28 ccw(c473.23,1074.28) 473.23,1050.81 ; 773.17,1445.98 ccw(c803.08,1445.98) 803.08,1416.07 ; 773.17,1445.98 v1(773.17,1416.07) 803.08,1416.07 ; 1537.1,131.17 ccw(c1557.56,131.17) 1557.56,110.72 ; 1537.1,131.17 v1(1537.1,110.72) 1557.56,110.72
  Bottom Layer w10: v1(385.77,1050.81) U3.5 ; v1@582.85,764.38 582.85,1282.43 716.49,1416.07 v1(773.17,1416.07) ; v1(583.2,609.02) v1(583.2,764.38) ; v1(699,744.14) 734.38,744.14 748.01,757.76 CL4.2 ; CL4.2@739.25,809.55 746.01,802.79 CL4.2@746.01,843.07 ; v1(811.53,1131.16) 811.53,1011.02 746.01,945.5 CL4.2@746.01,843.07 ; v1(944.77,688.46) 906.12,727.12 906.12,786.54 849.58,843.07 CL4.2 ; C23.2 1261.76,164.89 1315.93,110.72 v1(1537.1,110.72) 1760.85,110.72 v1(1829.13,178.99) ; v1(1289.2,611.98) C25.1 1354.61,574.98 1373.44,556.15 v1(1373.44,538.56) ; v1(1876.57,110.72) 1983.89,110.72 2156.06,282.88 2156.06,356.42 2136.57,375.9 C6.1 R17.1 ; CL4.2@746.01,843.07 CL4.2
  other v1: 1060.82,152.43 1583.15,175.4 1261.43,184.78 1388.77,186.91 1895.9,190.41 1732.86,199.68 1116.15,205.15 85.88,209.97 1290.21,244.6 702.26,267.54 889.25,283.88 136.44,312.48 1060.5,348.05 595.56,356 1129.77,391.74 919.78,392.99 120.97,452.86 1919.67,453.11 752.8,465.51 1749.02,502.43 675.58,535.71
  other v2: 1908.35,36.91 1186.54,38.64 396.02,40.23 50.44,44.95 1918.63,381.14 1315.03,405.19 1917.66,510.78
NetC3_1: C3.1 R24.1 U6.1 | length 494.2
  Top Layer w25: U6.1 1898.53,1417.06 1936.11,1454.63 C3.1 2036.79,1504.44 2103.96,1571.61 R24.1
NetC3_2: C3.2 C4.1 C20.2 C21.2 C22.2 CL1.2 D8.2 H1.4 R19.2 U6.5 U10.3 | length 1889
  Top Layer w15: R19.2 C20.2 C3.2
  Top Layer w30: U10.3 v4(1440.99,1461.22) 1538.71,1558.94 R19.2 ; C4.1 1521.09,1072.93 1558.33,1035.69 H1.4 1636.14,1134.62 1676.57,1175.05 U6.5@1742.2,1175.05 ; C22.2 1741.64,1660.47 1771.62,1690.45 CL1.2
  Bottom Layer w30: v4(1440.99,1461.22) 1440.99,1174.14 1472.16,1142.98 C4.1 ; CL1.2 1834.03,1824.1 1834.03,1876.79 1866.99,1909.75 D8.2
NetC4_2: C4.2 C18.2 C27.2 CL2.2 CL3.2 H1.5 L6.2 | length 647.5
  Top Layer w25: C18.2 v1(1213.2,817.35) ; C27.2 v1(1213.96,900.42) ; L6.2@1228.92,1142.98 C4.2 ; H1.5 C4.2@1321.18,1142.87
  Bottom Layer w25: CL2.2@1214.32,780.11 CL3.2 1237.62,1060.77 1262.71,1035.69 H1.5
NetC9_1: C9.1 U3.6 | length 76.5
  Top Layer w12: C9.1 v1(335.77,1129.75)
  Bottom Layer w12: v1(335.77,1129.75) U3.6
NetC17_1: C17.1 CL1.1 D8.1 H1.1 R13.1 R14.2 | length 2578.3
  Top Layer w25: CL1.1 1921.62,1846.48 1967.58,1892.43 1967.58,2020.57 2051.17,2104.16 R14.2
  Bottom Layer w15: 1841.42,740.41 1880.04,740.41 ; 1880.04,701.8 1880.04,740.41 ; 1880.04,740.41 1907.32,767.7 ; 1907.32,767.7 cw(c1841.42,833.64) 1907.27,767.65 cw(c1973.26,701.8) 1907.32,767.7
  Bottom Layer w25: 1841.42,740.41 cw(c1841.42,701.8) 1880.04,701.8
  Bottom Layer w30: C17.1 1531.37,740.41 H1.1 1841.42,740.41 ccw(c1841.42,833.64) 1907.27,767.65 ccw(c1973.26,701.8) 1880.04,701.8 R13.1 ; 1907.32,767.7 1946.32,806.69 1946.32,1599.06 1921.62,1623.75 CL1.1 1921.62,1846.97 1966.99,1892.34 D8.1
NetC17_2: C17.2 D7.2 R13.2 | length 254.1
  Top Layer w25: C17.2@1619.05,628.12 D7.2
  Bottom Layer w30: C17.2 R13.2@1746.02,628.28
NetC20_1: C20.1 U6.2 | length 185.5
  Top Layer w12: U6.2@1848.53,1330.08 U6.2
  Top Layer w25: U6.2 1848.53,1423.78 1875.33,1450.58 C20.1
NetC21_1: C21.1 D9.2 U6.3 | length 485.3
  Top Layer w25: U6.3 C21.1
  Bottom Layer w12: D9.2 D9.2@1799.05,1071.12
  Bottom Layer w30: D9.2 C21.1
NetC22_1: C22.1 R19.1 U6.4 U10.4 | length 618.7
  Top Layer w15: U10.4 v4(1389.74,1561.22) ; U6.4@1748.53,1330.08 U6.4
  Top Layer w25: C22.1 R19.1 1684.96,1384.8 1709.67,1360.09 U6.4
  Top Layer w30: v4(1621.63,1504.44) R19.1
  Bottom Layer w30: v4(1389.74,1561.22) 1564.85,1561.22 v4(1621.63,1504.44)
NetC24_1: C24.1 R12.1 R15.2 U8.1 | length 149.1
  Top Layer w15: R12.1@914.02,1362.81 C24.1 U8.1@914.02,1511.92
NetC24_2: C24.2 U8.2 U10.2 | length 188.8
  Top Layer w12: C24.2 U8.2@968.52,1508.89
  Top Layer w15: C24.2 1034.05,1468.6 1041.43,1461.22 U10.2
NetC27_1: C27.1 CL3.1 L4.2 L6.1 | length 489.5
  Top Layer w25: v3(1017.12,1003.61) L4.2 C27.1@1133.92,900.32 ; v3(1113.93,1060.79) 1143.56,1031.16 L6.1
  Bottom Layer w25: CL3.1 v3(1113.93,1060.79) ; v3(1017.12,1003.61) CL3.1@1017.12,1058.24
NetD2_1: D2.1 K1.2@1323.29,1277.29 Q1.3 | length 1136.3
  Top Layer w15: Q1.3 945.05,520.55 904.9,560.7 904.9,961.65 942.34,999.09 942.34,1058.29 1087.38,1203.34 1249.34,1203.34 K1.2@1323.29,1277.29 ; K1.2@1323.55,1277.54 D2.1
NetD3_1: D3.1 K2.2@908.11,1277.29 Q2.3 | length 1405.3
  Top Layer w15: v1(643.41,503.56) 824.64,322.33 Q2.3 ; v1(643.41,1106.64) 733.5,1196.73 827.55,1196.73 K2.2@908.11,1277.29 ; K2.2@908.33,1277.07 D3.1
  Bottom Layer w15: v1(643.41,503.56) v1(643.41,1106.64)
NetD4_1: D4.1 K3.2@492.93,1277.29 Q3.3 | length 1572.2
  Top Layer w20: v1(492.93,342.67) 711.48,124.12 Q3.3 ; K3.2@492.93,1277.29 D4.1@577.69,1277.29
  Bottom Layer w20: v1(492.93,342.67) K3.2@492.93,1277.29
NetD6_1: D6.1 H1.6 | length 167.3
  Top Layer w30: D6.1 1215.89,740.41 H1.6
NetD7_1: D7.1 H1.2 U6.8
NetD9_1: D9.1 H1.3 | length 162.4
  Bottom Layer w25: H1.3 D9.1@1798.53,937.26
NetF1_2: F1.2 接线柱1.1 | length 370.9
  Top Layer w120: 接线柱1.1@200.21,2101.1 接线柱1.1@200.21,2168
  Top Layer w150: 接线柱1.1@200.21,2101.1 303.66,1997.65 F1.2@303.66,1839.96
NetQ1_1: Q1.1 R3.2 R9.1 | length 89.9
  Top Layer w12: Q1.1@1045.61,494.42 R3.2
NetQ2_1: Q2.1 R4.2 R10.1 | length 92.4
  Top Layer w15: Q2.1@1043.1,293.71 R4.2
NetQ3_1: Q3.1 R5.2 R11.1 | length 104.3
  Top Layer w15: Q3.1 1040.6,92.99 R5.2
NetQ4_1: Q4.1 R2.1 R25.1 | length 120.8
  Top Layer w20: Q4.1 R2.1@682.14,689.58
NetQ4_3: Q4.3 U2.2 | length 112.5
  Top Layer w12: U2.2 450.39,702.29 Q4.3@475.48,727.37
NetR14_1: R14.1 R23.1 | length 81.5
  Top Layer w25: R23.1 R14.1@2103.86,2025.33
NetR20_2: R20.2 U10.1 | length 203.3
  Top Layer w12: U10.1@1123.89,1561.22 1176.67,1508.44 R20.2
NetR23_2: R23.2 R24.2 | length 76
  Top Layer w25: R24.2 R23.2@2103.96,1864.95
SPEAK: P3.6 R2.2 | length 1132
  Top Layer w12: R2.2 682.18,595.96 837.53,440.6 1157.47,440.6 v1(1182.87,415.2) ; v1(1409.13,365.14) 1498.86,365.14 1508.57,355.43 P3.6 P3.6@1675.33,355.43
  Bottom Layer w12: v1(1182.87,415.2) 1232.93,365.14 v1(1409.13,365.14)
TEMPERATURE: C6.2 P3.5 R16.2 R17.2 | length 566.2
  Top Layer w10: P3.5 1896.59,355.13 1915.57,336.14 v1(1915.57,229.01)
  Bottom Layer w10: v1(1915.57,229.01) 1955.77,188.81 1999.34,188.81 2056.01,245.48 R16.2 C6.2 R17.2
ZCP: P3.3
火线: F1.1 U3.1 U3.2 | length 498.3
  Top Layer w70: v1(260.77,1366.82) 260.77,1418.73 260.77,1430.23 303.66,1473.13 F1.1
  Bottom Layer w12: v1(235.77,1366.82) v1(260.77,1366.82) v1(285.76,1366.81)
  Bottom Layer w70: v1(260.77,1366.82) 260.77,1418.73 v1@260.77,1430.08 ; v1@260.77,1430.23 v1@260.77,1430.08 ; 299.25,1468.56 v1@260.77,1430.08 ; 303.57,1472.88 303.57,1546.73
  other v1: 273.17,1346.75 248.73,1347.92 235.34,1391.27 260.72,1391.5 285.63,1391.04 237.04,1413.06 261.95,1412.6 287.33,1412.83 283.43,1436.42 236.91,1437.3 259.84,1437.3 299.76,1457.26 250.91,1458.14 275.34,1458.14 303.55,1481.49 326.48,1481.49 279.95,1482.36 303.55,1508.74 326.48,1508.74 279.95,1509.61 303.55,1535.99 326.48,1535.99 279.95,1536.86 303.55,1562.91 326.48,1562.91 279.95,1563.78
  other v2: 324.19,1456.8
火线OUT: D5.2 D8.4 K1.3 K2.3 K3.3 U3.3 U3.4 | length 3290.9
  Top Layer w70: v1(385.76,1366.81) v1(403.41,1384.46) v1(424.38,1405.43) v1(443.42,1424.46) v1(462.69,1443.73) v1(480.33,1461.38) 492.93,1473.98 v1(492.93,1486.36) v1(492.93,1511.31) v1(492.93,1540.97) v1(492.93,1567.89) v1(492.93,1595.14) v1(492.93,1620.09) v1(492.93,1649.75) v1(492.93,1676.67) v1(492.93,1703.92) v1(492.93,1728.87) K3.3
  Bottom Layer w15: D8.4 D8.4@1866.99,2150.42
  Bottom Layer w20: K1.3 1502.43,1777.29 1534.61,1745.1 1636.46,1745.1 1731.23,1839.87 1731.23,1935.27 1788.65,1992.7 1788.65,2141.97 D5.2 1876.97,2160.4 D8.4@1866.99,2150.42
  Bottom Layer w70: v1(385.76,1366.81) v1(403.41,1384.46) v1(424.38,1405.43) v1(443.42,1424.46) v1(462.69,1443.73) v1(480.33,1461.38) 492.93,1473.98 492.93,1510.44 v1(492.93,1540.97) v1@492.93,1591.96 ; K3.3 v1@492.93,1731.93 ; K2.3 K2.3@908.11,1757.75 ; K1.3 1203.75,1657.75 1008.11,1657.75 ; v1@492.93,1591.96 ccw(c558.97,1591.71) 492.93,1591.73 v1(492.93,1595.14) v1(492.93,1620.09) v1(492.93,1649.75) v1(492.93,1676.67) v1(492.93,1703.92) v1(492.93,1728.87) v1@492.93,1731.93 ; v1@492.93,1591.97 cw(c558.97,1591.71) 558.97,1657.75 567.11,1657.75 ; v1@492.93,1731.93 ccw(c567.11,1731.93) 567.11,1657.75 ; 567.11,1657.75 808.11,1657.75 ; 808.11,1657.75 ccw(c808.11,1757.75) K2.3@908.11,1757.75 ; 808.11,1657.75 1008.11,1657.75 ; K2.3@908.11,1757.75 ccw(c1008.11,1757.75) 1008.11,1657.75
  other v1: 336.06,1341.29 360.32,1340.79 386.1,1340.95 361.68,1365.02 335.76,1366.81 419.48,1367.16 440.45,1388.13 336.58,1390.47 362.03,1390.13 387.2,1400.67 459.48,1407.16 408.17,1421.64 478.75,1426.43 427.21,1440.68 496.4,1444.07 446.47,1459.95 509.06,1463.56 466.57,1483.84 516.53,1485.49 516.53,1510.44 470.01,1511.31 516.53,1540.1 470.01,1540.97 516.53,1567.02 470.01,1567.89 516.53,1594.27 470.01,1595.14 516.53,1619.22 470.01,1620.09 516.53,1648.87 470.01,1649.75 516.53,1675.79 470.01,1676.67 516.53,1703.04 470.01,1703.92 516.53,1728 470.01,1728.87
零线: D5.1 D8.3 接线柱2.1 | length 1982.8
  Top Layer w25: v5(1649.23,1981.77) 1739.91,1981.77 1806.69,1914.99 1848.4,1914.99 1871.63,1938.22 1871.63,2018.63 2020.97,2167.98 D5.1
  Bottom Layer w12: D8.3 D8.3@1966.99,2156.87 ; D5.1@2020.97,2210.86 D5.1
  Bottom Layer w20: D8.3@1966.99,2156.87 D5.1@2020.97,2210.86
  Bottom Layer w25: 接线柱2.1@555.8,2101.1 555.8,1998.75 597.74,1956.81 691.02,1956.81 715.96,1981.77 v5(1649.23,1981.77) ; 接线柱2.1@555.8,2142.39 接线柱2.1@555.8,2168
pads on no net: K1.2@1321.71,1889.49 K2.2@906.53,1889.49 K3.2@491.36,1889.49 P3.7 P3.9 P3.11 U10.5

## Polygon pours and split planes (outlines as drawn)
GND on Top Layer "Top Layer-No Net" (solid, remove dead copper, pour order 2): 0,0 0,628.4 1115.33,628.4 1137.88,605.85 1367.24,605.85 1420.11,552.98 1940.89,552.98 1940.89,0
NetD7_1 on Top Layer "Top Layer-No Net" (solid, remove dead copper, pour order 6): 1867.51,1237.85 1977.34,1237.85 1977.34,1004.01 1978.88,971.44 1988.09,929.12 2008.24,885.94 2025.24,859.47 2051.71,829.52 2090.29,799.3 2144.98,773.39 2176.3,737.5 2176.3,291.17 1974.12,291.17 1974.12,552.98 1854.4,552.98 1854.4,684.84 ccw(c1818.85,684.84) 1818.85,720.39 1798.13,720.39 cw(c1798.13,754.95) 1763.57,754.95 ccw(c1707.37,754.95) 1707.37,811.15 1632.26,811.15 cw(c1632.26,836.94) 1606.47,836.94 cw(c1633.65,836.94) 1633.65,864.12 1704.6,864.12 ccw(c1704.6,898.23) 1738.7,898.23 1738.7,1036.14 cw(c1776.87,1036.14) 1776.87,1074.31 1806.45,1074.31 ccw(c1806.45,1117.43) 1849.57,1117.43 1849.57,1220.31 cw(c1867.1,1220.31) 1867.1,1237.84
GND on Bottom Layer "Top Layer-No Net" (solid, remove dead copper, pour order 4): 0,0 0,628.4 1367.24,628.4 1367.24,605.85 1420.11,552.98 1940.89,552.98 1940.89,0

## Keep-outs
Keep-Out Layer:
  lines w5: 0,0 0,744.4 24.42,773.35 ccw(c-37.96,1001.89) 198.93,1000.49 198.93,1294.29 ccw(c-40.79,1295.71) 40.95,1521.07 0,1557.7 0,2302 2176.3,2302 2176.3,1565.1 2147.57,1525.93 ccw(c2214.26,1298.6) 1977.36,1300 1977.36,1004.81 ccw(c2217.11,1003.35) 2145.17,774.64 2176.3,737.5 2176.3,0 1.4,0
  lines w31.5: 215.76,1280.18 402.29,1280.18 566.81,1444.71 566.81,1577.22 ; 359.42,1430.65 415.39,1486.62 415.39,1876.9 415.39,2176.79 ; 643.83,1988.57 689.13,2033.87 689.13,2208.02 ; 742.77,1937.1 845.64,1937.1 ; 760.48,1799.99 824.54,1799.99 869.84,1845.29 933.91,1845.29 ; 783.85,2015.85 1036.19,2015.85 1036.19,2191.12 ; 1131.88,2015.73 1399.53,2015.73 1399.53,2216.8 ; 1142.32,1945.39 1272.11,1945.39 ; 1177.31,1803.11 1241.37,1803.11 1286.67,1848.41 1350.74,1848.41 ; 1394.05,1202.85 1394.05,1094.28 1437.56,1050.77 1437.56,750.45 1367.24,680.13 1367.24,605.85 1420.11,552.98 1940.89,552.98 1974.12,552.98 1974.12,219.57 ; 1487.4,1212.98 1643.67,1212.98 1674.02,1243.33 1674.02,1325.89 1642.62,1357.29 ; 1493.45,2017.94 1752.91,2017.94 1752.91,2250.7 ; 1539.69,1806.75 1649.79,1806.75 1695.09,1852.05 1695.09,1923.99 1673.68,1945.39 1543.9,1945.39 ; 1567.63,694.53 1712.05,694.53 ; 1717.43,1718.59 1717.43,1775.91 1779.04,1837.53 1779.04,1897.42 ; 1821.99,1712.47 1867.29,1757.77 1867.29,1851.47 1912.6,1896.77 1912.6,2012.62 1912.65,2012.68 ; 1822.07,1946.74 1822.07,2117.87 ; 1913.89,2105.8 1913.89,2169.86 1944.4,2200.38 ; 1945.33,2202.3 1945.33,2288.24 ; 2073.07,2173.1 1912.65,2012.68 ; 1912.65,2012.68 1912.65,2012.68

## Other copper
Top Layer:
  region net 火线OUT: 335.74,1404.22 ccw(c335.74,1392.43) 323.96,1392.43 323.96,1341.23 ccw(c335.77,1341.23) 335.77,1329.42 397.83,1329.42 411.08,1342.67 411.08,1404.22
  text "注意KEEP-OUT层为板框和开槽" at -204.56,2529.81 h200
Bottom Layer:
  rectangle net 火线: 235.76,1341.02 287.09,1366.81
  rectangle net 火线OUT: 335.77,1329.42 385.77,1404.22
  rectangle net 火线: 235.77,1329.42 285.79,1346.61

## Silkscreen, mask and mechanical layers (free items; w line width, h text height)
Top Overlay:
  text "灯1" at 754.8,2213.81 h60 r90
  text "灯2" at 1117.33,2206.77 h60 r90
  text "灯3" at 1478.69,2206.38 h60 r90
  text "火线" at 66.32,2184.07 h60 r90
  text "零线" at 373.75,2183.9 h60 r90
  text "Wiscloud" at 119.44,217.95 h60
  text "V3.0" at 181.25,167.64 h50
  text "2018.12.11  批量" at 95,110.14 h50
Mechanical 15:
  circle w5: c83.28,1882.57 r98.43
  circle w5: c2073.04,103.43 r98.43
  circle w10: c2097.56,1868.92 r98.43
  lines w10: 0,2302 2176.3,0 ; 1.4,0 1.08,11.3 2165.31,2302 2097.56,2302 2097.56,1868.92 2097.56,1.67 ; 80.14,1.67 80.14,1868.92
